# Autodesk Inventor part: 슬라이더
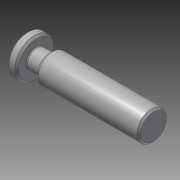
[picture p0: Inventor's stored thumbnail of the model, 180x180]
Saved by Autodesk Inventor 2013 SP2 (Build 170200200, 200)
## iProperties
Created: 2016-05
Part Number: 슬라이더
Document SubType Name: Modeling
Designer: mduedu
Density: 7.86 g/cm^3
Material: 강철, 연강
Author: mduedu
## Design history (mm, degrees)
sketch "스케치1"
  geometry: L1 (-7.5, 0)-(57.5, 0); L2 (57.5, 0)-(57.5, 7.5); L3 (57.5, 7.5)-(0, 7.5); L4 (-7.5, 0)-(-7.5, 10); L5 (-7.5, 10)-(-2.5, 10); L6 (-2.5, 10)-(-2.5, 5); L7 (-2.5, 5)-(3.5, 5); L8 (3.5, 5)-(6, 7.5); A1 r 7.5 centre (0, 0) between (0, 7.5) and (-7.5, 0); 1 further point
  constraints: 16 end point, 3 perpendicular, 2 horizontal, 2 parallel, 2 point on circle, 2 point on line, 2 tangent, 1 centre point, 1 coincident
  dimensions: "d0" = 15 diameter of A1; "d1" = 65 distance of L1.start L1.end; "d19" = 20 diameter of L5 L1; "d20" = 10 diameter of L7 L1; "d21" = 5 distance of L4.end L5.end; "d22" = 135 deg angle of L8 L7; "d23" = 6 distance of L6.end L7.end
revolve "회전1" stored, may be unused: angle "d4" = 90 deg
chamfer "모따기2" distance "d24" = 1; stored, may be unused: second distance "d25" = 2, angle "d26" = 45 deg
fillet "모깎기1" dims "d27" = 0.5
node "솔리드1"
